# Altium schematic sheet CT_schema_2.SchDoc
size 282 x 169 mm
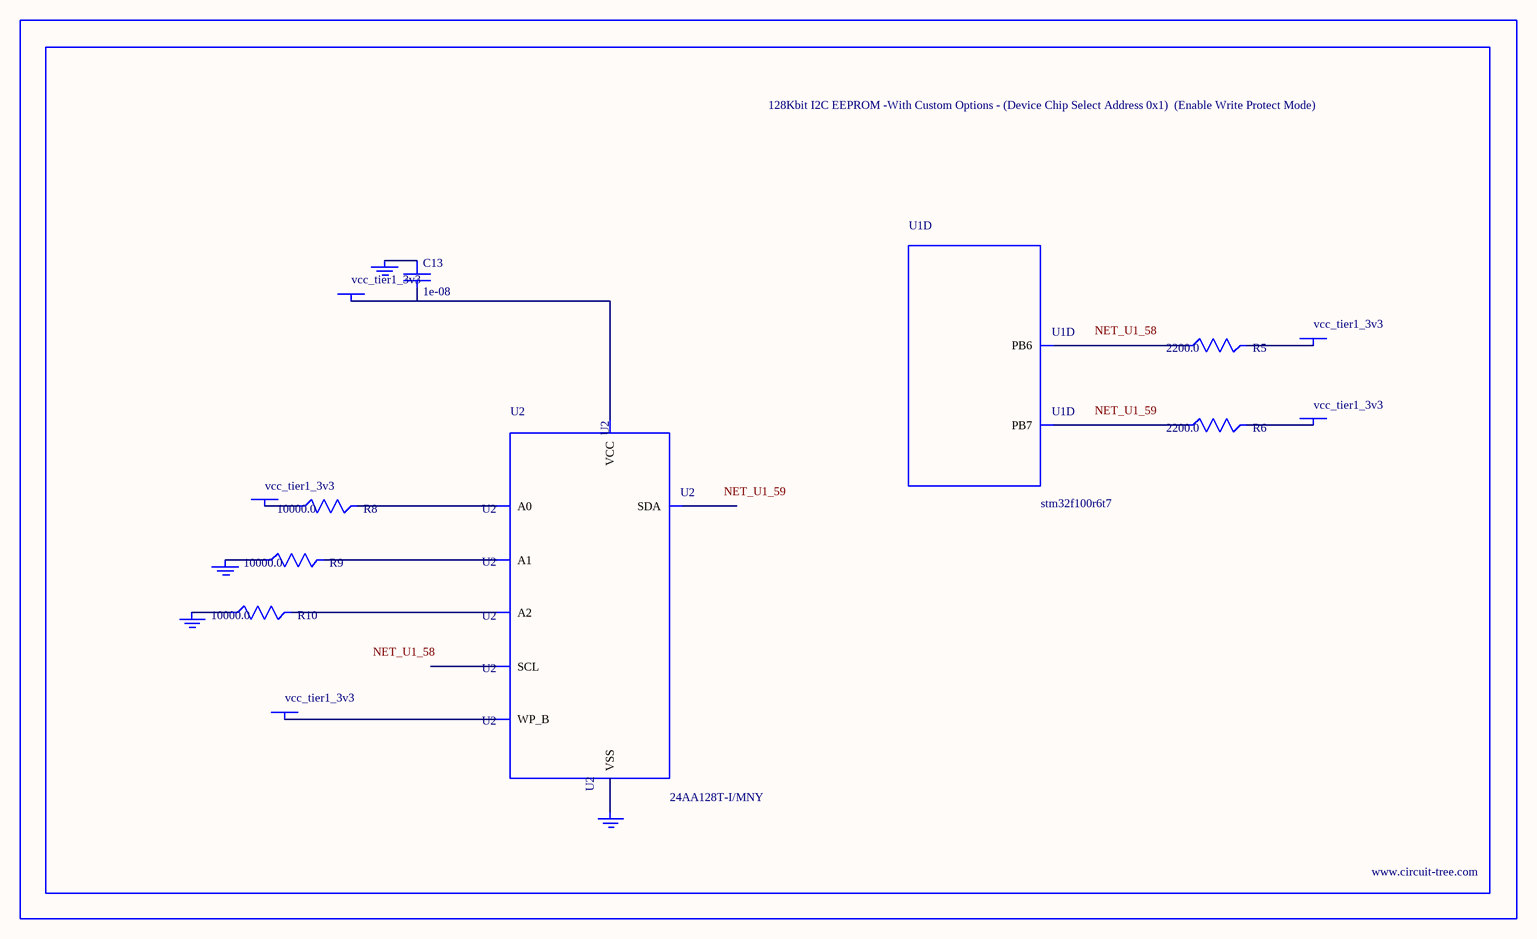
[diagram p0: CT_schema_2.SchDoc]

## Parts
BORDER1  (no value)
C13  1e-08  [C0402]
GND_INSTANCE_1_0  (no value)
GND_INSTANCE_1_1  (no value)
GND_INSTANCE_1_2  (no value)
GND_INSTANCE_1_3  (no value)
POWER_INSTANCE_1_0  vcc_tier1_3v3
POWER_INSTANCE_1_1  vcc_tier1_3v3
POWER_INSTANCE_1_2  vcc_tier1_3v3
POWER_INSTANCE_1_3  vcc_tier1_3v3
POWER_INSTANCE_1_4  vcc_tier1_3v3
R5  2200.0  [R0603]
R6  2200.0  [R0603]
R8  10000.0  [R0603]
R9  10000.0  [R0603]
R10  10000.0  [R0603]
U1  stm32f100r6t7  [LQFP64]  (part D of 5)
U2  24AA128T-I/MNY  [TDFN-8/6MM]

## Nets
NetC13_1: C13.1 GND_INSTANCE_1_2.0(GND)
NetC13_2: C13.2 POWER_INSTANCE_1_2.0(PWR) U2.8(VCC)
NetGND_INSTANCE_1_0_0: GND_INSTANCE_1_0.0(GND) R9.1
NetGND_INSTANCE_1_1_0: GND_INSTANCE_1_1.0(GND) R10.1
NetGND_INSTANCE_1_3_0: GND_INSTANCE_1_3.0(GND) U2.4(VSS)
NetPOWER_INSTANCE_1_0_0: POWER_INSTANCE_1_0.0(PWR) R8.1
NetPOWER_INSTANCE_1_1_0: POWER_INSTANCE_1_1.0(PWR) U2.7(WP_B)
NetPOWER_INSTANCE_1_3_0: POWER_INSTANCE_1_3.0(PWR) R5.2
NetPOWER_INSTANCE_1_4_0: POWER_INSTANCE_1_4.0(PWR) R6.2
NetR5_1: R5.1 U1.58(PB6)
NetR6_1: R6.1 U1.59(PB7)
NetR8_2: R8.2 U2.1(A0)
NetR9_2: R9.2 U2.2(A1)
NetR10_2: R10.2 U2.3(A2)

Not connected (* = marked no-connect by the designer): U2 5(SDA) 6(SCL)

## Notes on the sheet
- Labels drawn without touching a wire or pin: NET_U1_58, NET_U1_59

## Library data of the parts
BORDER1 = BORDER_PAGE1
C13 = C0402C103K3RAC
GND_INSTANCE_1_0-GND_INSTANCE_1_3 = GND
POWER_INSTANCE_1_0-POWER_INSTANCE_1_4 = PWR
R5 R6 = RC0603JR-072K2L
R8-R10 = RC0603JR-0710KL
